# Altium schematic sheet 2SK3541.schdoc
size 127 x 101 mm
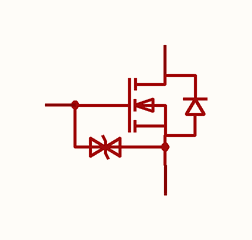
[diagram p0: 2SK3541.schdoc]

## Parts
Q?  2sk3541_c504051  [SOT-723_L1.2-W0.8-P0.40-LS1.2-BR]  (value not drawn)

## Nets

Not connected (* = marked no-connect by the designer): Q? 1(G) 2(S) 3(D)

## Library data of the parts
Q? = 2sk3541_c504051: 数量:1个N沟道;漏源电压(Vdss):30V;连续漏极电流(Id):100mA;导通电阻(RDS(on)):13Ω@2.5V;耗散功率(Pd):150mW;阈值电压(Vgs(th)):800mV;; Manufacturer: CJ(江苏长电/长晶); AddInBom: yes; ModelId: abccde1e67074d7481274a37cf5c97f0; ModelName: SOT-723-3P_L1.2-W0.8-H0.6-LS1.2-P0.40; ModelTransform: 47.244,47.244,0,180,0,0,0,0,0; Number: 1个N沟道; Drain to Source Voltage: 30V; Current - Continuous Drain(Id): 100mA; Pd - Power Dissipation: 150mW; Gate Threshold Voltage (Vgs(th)): 800mV; Input Capacitance(Ciss): 13pF; Reverse Transfer Capacitance (Crss@Vds): 4pF; Type: N沟道; Output Capacitance(Coss): 9pF; Vgs: ±20V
